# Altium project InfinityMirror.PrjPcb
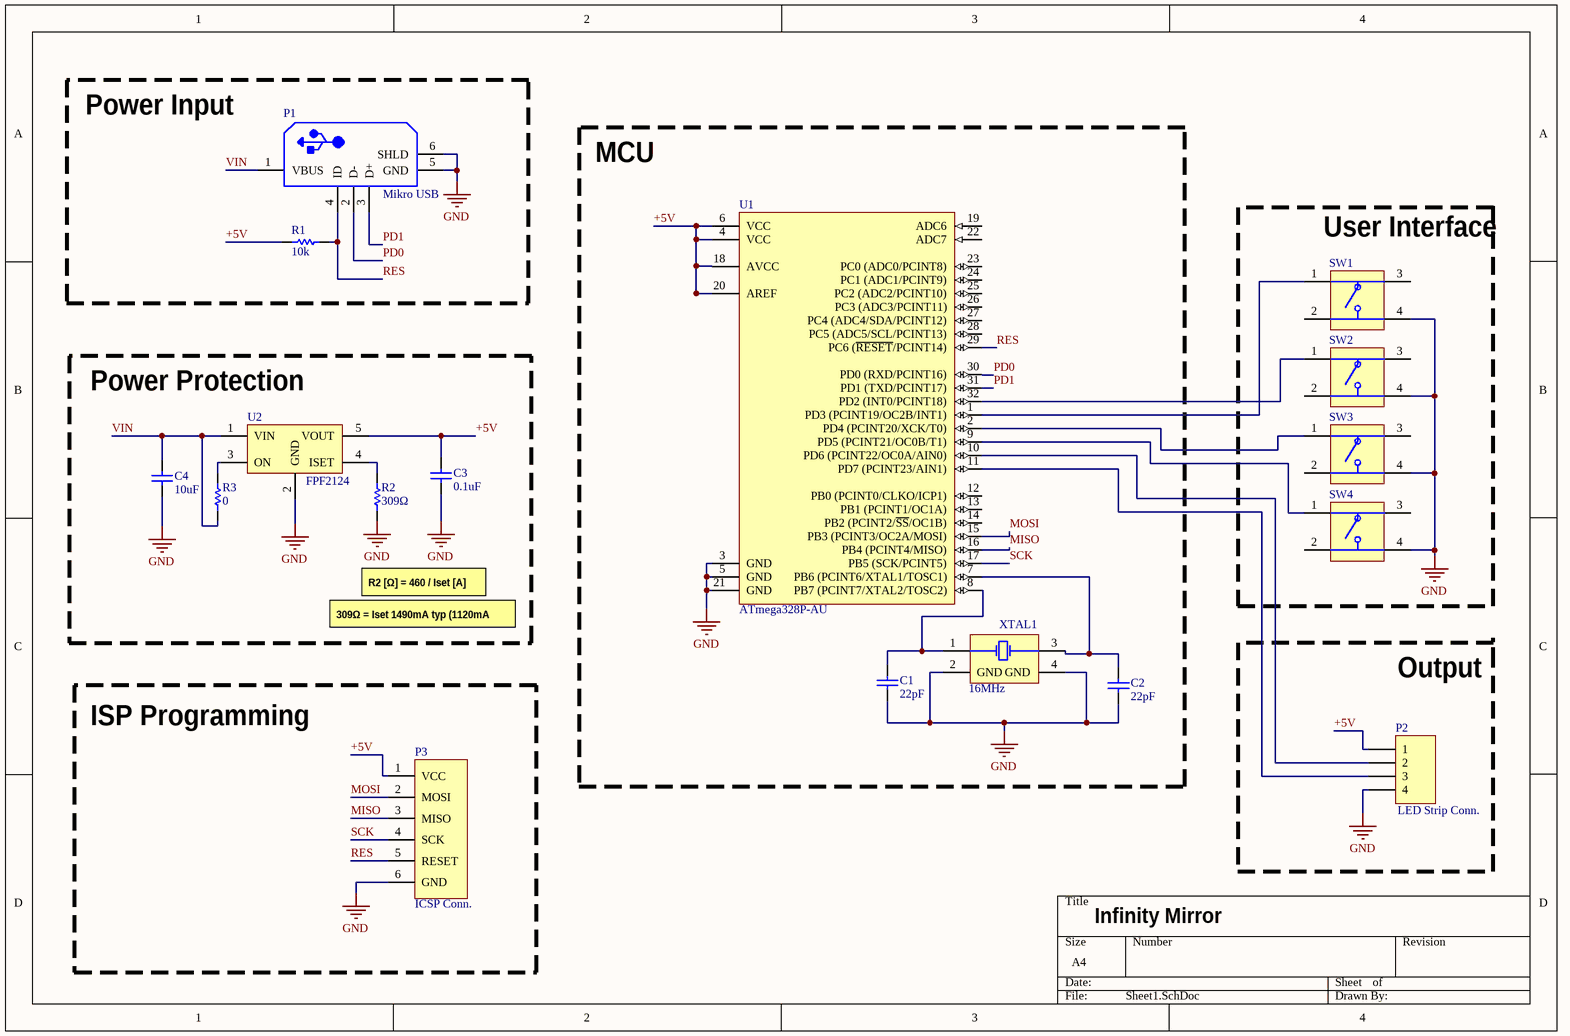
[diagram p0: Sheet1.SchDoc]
1 sheet, 17 parts. Net scope: global (net labels, ports and power ports of the same name join across sheets).
Board file: PCB1.PcbDoc

## Sheet Sheet1.SchDoc
size A4

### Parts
C1  22pF  [CAP0805]
C2  22pF  [CAP0805]
C3  0.1uF  [CAP0805]
C4  10uF  [CAP0805]
P1  Mikro USB  [USB Type B]
P2  LED Strip Conn.  [HDR1X4H]
P3  ICSP Conn.  [ICSP Conn.]
R1  10k  [RES0805]
R2  309Ω  [RES0805]
R3  0  [RES0805]
SW1  Button  [Button]  (value not drawn)
SW2  Button  [Button]  (value not drawn)
SW3  Button  [Button]  (value not drawn)
SW4  Button  [Button]  (value not drawn)
U1  ATmega328P-AU  [Atmega328P-AU]
U2  FPF2124  [SOT23-5]
XTAL1  16MHz  [Crystal 3.2x2.5]

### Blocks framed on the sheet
Power Input: P1 R1
MCU: C1 C2 U1 XTAL1
Power Protection: C3 C4 R2 R3 U2
ISP Programming: P3

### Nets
GND: C1.1 C2.1 C3.1 C4.1 P1.5(GND) P1.6(SHLD) P2.4 P3.6(GND) R2.1 SW1.4(B') SW2.4(B') SW3.4(B') SW4.4(B') U1.3(GND) U1.5(GND) U1.21(GND) U2.2(GND) XTAL1.2(GND) XTAL1.4(GND)
+5V: C3.2 P2.1 P3.1(VCC) R1.1 U1.4(VCC) U1.6(VCC) U1.18(AVCC) U1.20(AREF) U2.5(VOUT)
MISO: P3.3(MISO) U1.16(PB4_(PCINT4/MISO))
MOSI: P3.2(MOSI) U1.15(PB3_(PCINT3/OC2A/MOSI))
PD0: P1.2(D-) U1.30(PD0_(RXD/PCINT16))
PD1: P1.3(D+) U1.31(PD1_(TXD/PCINT17))
RES: P1.4(ID) P3.5(RESET) R1.2 U1.29(PC6_(~{RESET}/PCINT14))
SCK: P3.4(SCK) U1.17(PB5_(SCK/PCINT5))
VIN: C4.2 P1.1(VBUS) R3.1 U2.1(VIN)
NetC1_2: C1.2 U1.8(PB7_(PCINT7/XTAL2/TOSC2)) XTAL1.1(X1)
NetC2_2: C2.2 U1.7(PB6_(PCINT6/XTAL1/TOSC1)) XTAL1.3(X2)
NetP2_2: P2.2 U1.10(PD6_(PCINT22/OC0A/AIN0))
NetP2_3: P2.3 U1.11(PD7_(PCINT23/AIN1))
NetR2_2: R2.2 U2.4(ISET)
NetR3_2: R3.2 U2.3(ON)
NetSW1_1: SW1.1(A) U1.1(PD3_(PCINT19/OC2B/INT1))
NetSW2_1: SW2.1(A) U1.32(PD2_(INT0/PCINT18))
NetSW3_1: SW3.1(A) U1.2(PD4_(PCINT20/XCK/T0))
NetSW4_1: SW4.1(A) U1.9(PD5_(PCINT21/OC0B/T1))

Not connected (* = marked no-connect by the designer): SW1 2(B) 3(A'); SW2 2(B) 3(A'); SW3 2(B) 3(A'); SW4 2(B) 3(A'); U1 12(PB0_(PCINT0/CLKO/ICP1)) 13(PB1_(PCINT1/OC1A)) 14(PB2_(PCINT2/~{SS}/OC1B)) 19(ADC6) 22(ADC7) 23(PC0_(ADC0/PCINT8)) 24(PC1_(ADC1/PCINT9)) 25(PC2_(ADC2/PCINT10)) 26(PC3_(ADC3/PCINT11)) 27(PC4_(ADC4/SDA/PCINT12)) 28(PC5_(ADC5/SCL/PCINT13))

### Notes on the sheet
- (near SW1) User Interface
- 309Ω = Iset 1490mA typ (1120mA min)
- R2 [Ω] = 460 / Iset [A]
- Output
- Infinity Mirror

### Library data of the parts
C1-C4 = Cap: 0603
P2 = Header 4H: Header, 4-Pin, Right Angle
R1-R3 = Resistor: 0603
U1 = MC-8B-ATM48-SQ32: 8-bit AVR Microcontroller, 32KB Flash, 1KB EEPROM, 2KB SRAM, 32-pin TQFP, Industrial Grade (-40°C to 85°C)
XTAL1 = Crystal4Pin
